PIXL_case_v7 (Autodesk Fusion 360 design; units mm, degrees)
part number: 0.96Oled_W_4_Buttons
base_feature "Base Feature"
work_plane "WorkPlane1" AlongDistance -6.5 ExtraOffset 0
sketch "Sketch1" plane through (0, 0, -6.5) normal (0, 0, 1) x axis (1, 0, 0)
  line L1 (24.2, -27.5) -> (-24.2, -27.5)
  line L2 (24.2, 15.7) -> (24.2, -27.5)
  line L3 (-24.2, 15.7) -> (24.2, 15.7)
  line L4 (-24.2, -27.5) -> (-24.2, 15.7)
extrude "Extrude1" new body sketch "Sketch1" along normal blind 11.8
fillet "Fillet1" radius 5
fillet "Fillet2" radius 1.4
work_plane "WorkPlane2" AlongDistance -6.5 ExtraOffset 0
sketch "Sketch2" plane through (0, 0, -6.5) normal (0, 0, 1) x axis (1, 0, 0)
  line L1 (22.2, -25.5) -> (-22.2, -25.5)
  line L2 (22.2, 13.7) -> (22.2, -25.5)
  line L3 (-22.2, 13.7) -> (22.2, 13.7)
  line L4 (-22.2, -25.5) -> (-22.2, 13.7)
extrude "Extrude2" cut sketch "Sketch2" along normal blind 9.3
fillet "Fillet3" radius 1.7
work_plane "WorkPlane3" AlongDistance 2.79 ExtraOffset 0
sketch "Sketch3" plane through (0, 0, 2.79) normal (0, 0, 1) x axis (1, 0, 0)
  line L1 (20.7, -11.3) -> (11, -11.3)
  line L2 (20.7, 11.7) -> (20.7, -11.3)
  line L3 (11, 11.7) -> (20.7, 11.7)
  line L4 (11, -11.3) -> (11, 11.7)
extrude "Extrude3" cut sketch "Sketch3" along normal blind 1.56
work_plane "WorkPlane4" AlongDistance 2.79 ExtraOffset 0
sketch "Sketch4" plane through (0, 0, 2.79) normal (0, 0, 1) x axis (1, 0, 0)
  line L1 (10, 9.6) -> (-10.8, 9.6)
  line L2 (10, 12.2) -> (10, 9.6)
  line L3 (-10.8, 12.2) -> (10, 12.2)
  line L4 (-10.8, 9.6) -> (-10.8, 12.2)
extrude "Extrude4" cut sketch "Sketch4" along normal blind 0.91
work_plane "WorkPlane5" AlongDistance 4.34 ExtraOffset 0
sketch "Sketch5" plane through (0, 0, 4.34) normal (0, 0, 1) x axis (1, 0, 0)
  line L1 (12.1, 5.6) -> (11.5, 5.6)
  line L2 (12.1, 11.8) -> (12.1, 5.6)
  line L3 (11.5, 11.8) -> (12.1, 11.8)
  line L4 (11.5, 5.6) -> (11.5, 11.8)
extrude "Extrude5" cut sketch "Sketch5" along normal blind 1.06
work_plane "WorkPlane6" AlongDistance 4.34 ExtraOffset 0
sketch "Sketch6" plane through (0, 0, 4.34) normal (0, 0, 1) x axis (1, 0, 0)
  line L1 (19.6, 11.2) -> (11.5, 11.2)
  line L2 (19.6, 11.8) -> (19.6, 11.2)
  line L3 (11.5, 11.8) -> (19.6, 11.8)
  line L4 (11.5, 11.2) -> (11.5, 11.8)
extrude "Extrude6" cut sketch "Sketch6" along normal blind 1.06
work_plane "WorkPlane7" AlongDistance 4.34 ExtraOffset 0
sketch "Sketch7" plane through (0, 0, 4.34) normal (0, 0, 1) x axis (1, 0, 0)
  line L1 (19.6, 5.6) -> (11.5, 5.6)
  line L2 (19.6, 6.2) -> (19.6, 5.6)
  line L3 (11.5, 6.2) -> (19.6, 6.2)
  line L4 (11.5, 5.6) -> (11.5, 6.2)
extrude "Extrude7" cut sketch "Sketch7" along normal blind 1.06
work_plane "WorkPlane8" AlongDistance 4.34 ExtraOffset 0
sketch "Sketch8" plane through (0, 0, 4.34) normal (0, 0, 1) x axis (1, 0, 0)
  line L1 (12.1, -0.07) -> (11.5, -0.07)
  line L2 (12.1, 6.13) -> (12.1, -0.07)
  line L3 (11.5, 6.13) -> (12.1, 6.13)
  line L4 (11.5, -0.07) -> (11.5, 6.13)
extrude "Extrude8" cut sketch "Sketch8" along normal blind 1.06
work_plane "WorkPlane9" AlongDistance 4.34 ExtraOffset 0
sketch "Sketch9" plane through (0, 0, 4.34) normal (0, 0, 1) x axis (1, 0, 0)
  line L1 (19.6, 5.53) -> (11.5, 5.53)
  line L2 (19.6, 6.13) -> (19.6, 5.53)
  line L3 (11.5, 6.13) -> (19.6, 6.13)
  line L4 (11.5, 5.53) -> (11.5, 6.13)
extrude "Extrude9" cut sketch "Sketch9" along normal blind 1.06
work_plane "WorkPlane10" AlongDistance 4.34 ExtraOffset 0
sketch "Sketch10" plane through (0, 0, 4.34) normal (0, 0, 1) x axis (1, 0, 0)
  line L1 (19.6, -0.07) -> (11.5, -0.07)
  line L2 (19.6, 0.53) -> (19.6, -0.07)
  line L3 (11.5, 0.53) -> (19.6, 0.53)
  line L4 (11.5, -0.07) -> (11.5, 0.53)
extrude "Extrude10" cut sketch "Sketch10" along normal blind 1.06
work_plane "WorkPlane11" AlongDistance 4.34 ExtraOffset 0
sketch "Sketch11" plane through (0, 0, 4.34) normal (0, 0, 1) x axis (1, 0, 0)
  line L1 (12.1, -5.73) -> (11.5, -5.73)
  line L2 (12.1, 0.47) -> (12.1, -5.73)
  line L3 (11.5, 0.47) -> (12.1, 0.47)
  line L4 (11.5, -5.73) -> (11.5, 0.47)
extrude "Extrude11" cut sketch "Sketch11" along normal blind 1.06
work_plane "WorkPlane12" AlongDistance 4.34 ExtraOffset 0
sketch "Sketch12" plane through (0, 0, 4.34) normal (0, 0, 1) x axis (1, 0, 0)
  line L1 (19.6, -0.13) -> (11.5, -0.13)
  line L2 (19.6, 0.47) -> (19.6, -0.13)
  line L3 (11.5, 0.47) -> (19.6, 0.47)
  line L4 (11.5, -0.13) -> (11.5, 0.47)
extrude "Extrude12" cut sketch "Sketch12" along normal blind 1.06
work_plane "WorkPlane13" AlongDistance 4.34 ExtraOffset 0
sketch "Sketch13" plane through (0, 0, 4.34) normal (0, 0, 1) x axis (1, 0, 0)
  line L1 (19.6, -5.73) -> (11.5, -5.73)
  line L2 (19.6, -5.13) -> (19.6, -5.73)
  line L3 (11.5, -5.13) -> (19.6, -5.13)
  line L4 (11.5, -5.73) -> (11.5, -5.13)
extrude "Extrude13" cut sketch "Sketch13" along normal blind 1.06
work_plane "WorkPlane14" AlongDistance 4.34 ExtraOffset 0
sketch "Sketch14" plane through (0, 0, 4.34) normal (0, 0, 1) x axis (1, 0, 0)
  line L1 (12.1, -11.4) -> (11.5, -11.4)
  line L2 (12.1, -5.2) -> (12.1, -11.4)
  line L3 (11.5, -5.2) -> (12.1, -5.2)
  line L4 (11.5, -11.4) -> (11.5, -5.2)
extrude "Extrude14" cut sketch "Sketch14" along normal blind 1.06
work_plane "WorkPlane15" AlongDistance 4.34 ExtraOffset 0
sketch "Sketch15" plane through (0, 0, 4.34) normal (0, 0, 1) x axis (1, 0, 0)
  line L1 (19.6, -5.8) -> (11.5, -5.8)
  line L2 (19.6, -5.2) -> (19.6, -5.8)
  line L3 (11.5, -5.2) -> (19.6, -5.2)
  line L4 (11.5, -5.8) -> (11.5, -5.2)
extrude "Extrude15" cut sketch "Sketch15" along normal blind 1.06
work_plane "WorkPlane16" AlongDistance 4.34 ExtraOffset 0
sketch "Sketch16" plane through (0, 0, 4.34) normal (0, 0, 1) x axis (1, 0, 0)
  line L1 (19.6, -11.4) -> (11.5, -11.4)
  line L2 (19.6, -10.8) -> (19.6, -11.4)
  line L3 (11.5, -10.8) -> (19.6, -10.8)
  line L4 (11.5, -11.4) -> (11.5, -10.8)
extrude "Extrude16" cut sketch "Sketch16" along normal blind 1.06
work_plane "WorkPlane17" AlongDistance 4.34 ExtraOffset 0
sketch "Sketch17" plane through (0, 0, 4.34) normal (0, 0, 1) x axis (1, 0, 0)
  line L1 (20.7, 6.2) -> (18.4, 6.2)
  line L2 (20.7, 11.2) -> (20.7, 6.2)
  line L3 (18.4, 11.2) -> (20.7, 11.2)
  line L4 (18.4, 6.2) -> (18.4, 11.2)
extrude "Extrude17" cut sketch "Sketch17" along normal blind 0.46
work_plane "WorkPlane18" AlongDistance 4.34 ExtraOffset 0
sketch "Sketch18" plane through (0, 0, 4.34) normal (0, 0, 1) x axis (1, 0, 0)
  line L1 (20.7, 0.53) -> (18.4, 0.53)
  line L2 (20.7, 5.53) -> (20.7, 0.53)
  line L3 (18.4, 5.53) -> (20.7, 5.53)
  line L4 (18.4, 0.53) -> (18.4, 5.53)
extrude "Extrude18" cut sketch "Sketch18" along normal blind 0.46
work_plane "WorkPlane19" AlongDistance 4.34 ExtraOffset 0
sketch "Sketch19" plane through (0, 0, 4.34) normal (0, 0, 1) x axis (1, 0, 0)
  line L1 (20.7, -5.13) -> (18.4, -5.13)
  line L2 (20.7, -0.13) -> (20.7, -5.13)
  line L3 (18.4, -0.13) -> (20.7, -0.13)
  line L4 (18.4, -5.13) -> (18.4, -0.13)
extrude "Extrude19" cut sketch "Sketch19" along normal blind 0.46
work_plane "WorkPlane20" AlongDistance 4.34 ExtraOffset 0
sketch "Sketch20" plane through (0, 0, 4.34) normal (0, 0, 1) x axis (1, 0, 0)
  line L1 (20.7, -10.8) -> (18.4, -10.8)
  line L2 (20.7, -5.8) -> (20.7, -10.8)
  line L3 (18.4, -5.8) -> (20.7, -5.8)
  line L4 (18.4, -10.8) -> (18.4, -5.8)
extrude "Extrude20" cut sketch "Sketch20" along normal blind 0.46
work_plane "WorkPlane21" AlongDistance 2.79 ExtraOffset 0
sketch "Sketch21" plane through (0, 0, 2.79) normal (0, 0, 1) x axis (1, 0, 0)
  line L1 (7, -6.6) -> (-16.3, -6.6)
  line L2 (7, 6.4) -> (7, -6.6)
  line L3 (-16.3, 6.4) -> (7, 6.4)
  line L4 (-16.3, -6.6) -> (-16.3, 6.4)
extrude "Extrude21" cut sketch "Sketch21" along normal blind 2.61
chamfer "Chamfer1" distance 1.2
work_plane "WorkPlane22" AlongDistance 1.6 ExtraOffset 0
sketch "Sketch22" plane through (0, 0, 1.6) normal (0, 0, 1) x axis (1, 0, 0)
  circle C1 centre (-20.5, -12) radius 1.5
extrude "Extrude22" add sketch "Sketch22" along normal blind 1.21
work_plane "WorkPlane23" AlongDistance 0.3 ExtraOffset 0
sketch "Sketch23" plane through (0, 0, 0.3) normal (0, 0, 1) x axis (1, 0, 0)
  circle C1 centre (-20.5, -12) radius 0.88
extrude "Extrude23" add sketch "Sketch23" along normal blind 1.31
work_plane "WorkPlane24" AlongDistance 1.6 ExtraOffset 0
sketch "Sketch24" plane through (0, 0, 1.6) normal (0, 0, 1) x axis (1, 0, 0)
  circle C1 centre (-20.5, 12) radius 1.5
extrude "Extrude24" add sketch "Sketch24" along normal blind 1.21
work_plane "WorkPlane25" AlongDistance 0.3 ExtraOffset 0
sketch "Sketch25" plane through (0, 0, 0.3) normal (0, 0, 1) x axis (1, 0, 0)
  circle C1 centre (-20.5, 12) radius 0.88
extrude "Extrude25" add sketch "Sketch25" along normal blind 1.31
work_plane "WorkPlane26" AlongDistance 1.6 ExtraOffset 0
sketch "Sketch26" plane through (0, 0, 1.6) normal (0, 0, 1) x axis (1, 0, 0)
  circle C1 centre (20.5, -12) radius 1.5
extrude "Extrude26" add sketch "Sketch26" along normal blind 1.21
work_plane "WorkPlane27" AlongDistance 0.3 ExtraOffset 0
sketch "Sketch27" plane through (0, 0, 0.3) normal (0, 0, 1) x axis (1, 0, 0)
  circle C1 centre (20.5, -12) radius 0.88
extrude "Extrude27" add sketch "Sketch27" along normal blind 1.31
work_plane "WorkPlane28" AlongDistance 1.6 ExtraOffset 0
sketch "Sketch28" plane through (0, 0, 1.6) normal (0, 0, 1) x axis (1, 0, 0)
  circle C1 centre (20.5, 12) radius 1.5
extrude "Extrude28" add sketch "Sketch28" along normal blind 1.21
work_plane "WorkPlane29" AlongDistance 0.3 ExtraOffset 0
sketch "Sketch29" plane through (0, 0, 0.3) normal (0, 0, 1) x axis (1, 0, 0)
  circle C1 centre (20.5, 12) radius 0.88
extrude "Extrude29" add sketch "Sketch29" along normal blind 1.31
work_plane "WorkPlane30" AlongDistance 5.3 ExtraOffset 0
sketch "Sketch30" plane through (0, 0, 5.3) normal (0, 0, 1) x axis (1, 0, 0)
  line L1 (-16.5, -17.8) -> (-19.8, -17.8)
  line L2 (-16.5, -16.7) -> (-16.5, -17.8)
  line L3 (-19.8, -16.7) -> (-16.5, -16.7)
  line L4 (-19.8, -17.8) -> (-19.8, -16.7)
  line L5 (-18.7, -18.9) -> (-19.8, -18.9)
  line L6 (-18.7, -17.8) -> (-18.7, -18.9)
  line L7 (-19.8, -17.8) -> (-18.7, -17.8)
  line L8 (-19.8, -18.9) -> (-19.8, -17.8)
  line L9 (-15.4, -18.9) -> (-16.5, -18.9)
  line L10 (-15.4, -17.8) -> (-15.4, -18.9)
  line L11 (-16.5, -17.8) -> (-15.4, -17.8)
  line L12 (-16.5, -18.9) -> (-16.5, -17.8)
  line L13 (-18.7, -20) -> (-19.8, -20)
  line L14 (-18.7, -18.9) -> (-18.7, -20)
  line L15 (-19.8, -18.9) -> (-18.7, -18.9)
  line L16 (-19.8, -20) -> (-19.8, -18.9)
  line L17 (-15.4, -20) -> (-16.5, -20)
  line L18 (-15.4, -18.9) -> (-15.4, -20)
  line L19 (-16.5, -18.9) -> (-15.4, -18.9)
  line L20 (-16.5, -20) -> (-16.5, -18.9)
  line L21 (-16.5, -21.1) -> (-19.8, -21.1)
  line L22 (-16.5, -20) -> (-16.5, -21.1)
  line L23 (-19.8, -20) -> (-16.5, -20)
  line L24 (-19.8, -21.1) -> (-19.8, -20)
  line L25 (-18.7, -22.2) -> (-19.8, -22.2)
  line L26 (-18.7, -21.1) -> (-18.7, -22.2)
  line L27 (-19.8, -21.1) -> (-18.7, -21.1)
  line L28 (-19.8, -22.2) -> (-19.8, -21.1)
  line L29 (-18.7, -23.3) -> (-19.8, -23.3)
  line L30 (-18.7, -22.2) -> (-18.7, -23.3)
  line L31 (-19.8, -22.2) -> (-18.7, -22.2)
  line L32 (-19.8, -23.3) -> (-19.8, -22.2)
  line L33 (-13.2, -17.8) -> (-14.3, -17.8)
  line L34 (-13.2, -16.7) -> (-13.2, -17.8)
  line L35 (-14.3, -16.7) -> (-13.2, -16.7)
  line L36 (-14.3, -17.8) -> (-14.3, -16.7)
  line L37 (-13.2, -20) -> (-14.3, -20)
  line L38 (-13.2, -18.9) -> (-13.2, -20)
  line L39 (-14.3, -18.9) -> (-13.2, -18.9)
  line L40 (-14.3, -20) -> (-14.3, -18.9)
  line L41 (-13.2, -21.1) -> (-14.3, -21.1)
  line L42 (-13.2, -20) -> (-13.2, -21.1)
  line L43 (-14.3, -20) -> (-13.2, -20)
  line L44 (-14.3, -21.1) -> (-14.3, -20)
  line L45 (-13.2, -22.2) -> (-14.3, -22.2)
  line L46 (-13.2, -21.1) -> (-13.2, -22.2)
  line L47 (-14.3, -21.1) -> (-13.2, -21.1)
  line L48 (-14.3, -22.2) -> (-14.3, -21.1)
  line L49 (-13.2, -23.3) -> (-14.3, -23.3)
  line L50 (-13.2, -22.2) -> (-13.2, -23.3)
  line L51 (-14.3, -22.2) -> (-13.2, -22.2)
  line L52 (-14.3, -23.3) -> (-14.3, -22.2)
  line L53 (-11, -17.8) -> (-12.1, -17.8)
  line L54 (-11, -16.7) -> (-11, -17.8)
  line L55 (-12.1, -16.7) -> (-11, -16.7)
  line L56 (-12.1, -17.8) -> (-12.1, -16.7)
  line L57 (-7.7, -17.8) -> (-8.8, -17.8)
  line L58 (-7.7, -16.7) -> (-7.7, -17.8)
  line L59 (-8.8, -16.7) -> (-7.7, -16.7)
  line L60 (-8.8, -17.8) -> (-8.8, -16.7)
  line L61 (-11, -18.9) -> (-12.1, -18.9)
  line L62 (-11, -17.8) -> (-11, -18.9)
  line L63 (-12.1, -17.8) -> (-11, -17.8)
  line L64 (-12.1, -18.9) -> (-12.1, -17.8)
  line L65 (-7.7, -18.9) -> (-8.8, -18.9)
  line L66 (-7.7, -17.8) -> (-7.7, -18.9)
  line L67 (-8.8, -17.8) -> (-7.7, -17.8)
  line L68 (-8.8, -18.9) -> (-8.8, -17.8)
  line L69 (-8.8, -20) -> (-11, -20)
  line L70 (-8.8, -18.9) -> (-8.8, -20)
  line L71 (-11, -18.9) -> (-8.8, -18.9)
  line L72 (-11, -20) -> (-11, -18.9)
  line L73 (-8.8, -21.1) -> (-11, -21.1)
  line L74 (-8.8, -20) -> (-8.8, -21.1)
  line L75 (-11, -20) -> (-8.8, -20)
  line L76 (-11, -21.1) -> (-11, -20)
  line L77 (-11, -22.2) -> (-12.1, -22.2)
  line L78 (-11, -21.1) -> (-11, -22.2)
  line L79 (-12.1, -21.1) -> (-11, -21.1)
  line L80 (-12.1, -22.2) -> (-12.1, -21.1)
  line L81 (-7.7, -22.2) -> (-8.8, -22.2)
  line L82 (-7.7, -21.1) -> (-7.7, -22.2)
  line L83 (-8.8, -21.1) -> (-7.7, -21.1)
  line L84 (-8.8, -22.2) -> (-8.8, -21.1)
  line L85 (-11, -23.3) -> (-12.1, -23.3)
  line L86 (-11, -22.2) -> (-11, -23.3)
  line L87 (-12.1, -22.2) -> (-11, -22.2)
  line L88 (-12.1, -23.3) -> (-12.1, -22.2)
  line L89 (-7.7, -23.3) -> (-8.8, -23.3)
  line L90 (-7.7, -22.2) -> (-7.7, -23.3)
  line L91 (-8.8, -22.2) -> (-7.7, -22.2)
  line L92 (-8.8, -23.3) -> (-8.8, -22.2)
  line L93 (-5.5, -17.8) -> (-6.6, -17.8)
  line L94 (-5.5, -16.7) -> (-5.5, -17.8)
  line L95 (-6.6, -16.7) -> (-5.5, -16.7)
  line L96 (-6.6, -17.8) -> (-6.6, -16.7)
  line L97 (-5.5, -18.9) -> (-6.6, -18.9)
  line L98 (-5.5, -17.8) -> (-5.5, -18.9)
  line L99 (-6.6, -17.8) -> (-5.5, -17.8)
  line L100 (-6.6, -18.9) -> (-6.6, -17.8)
  line L101 (-5.5, -20) -> (-6.6, -20)
  line L102 (-5.5, -18.9) -> (-5.5, -20)
  line L103 (-6.6, -18.9) -> (-5.5, -18.9)
  line L104 (-6.6, -20) -> (-6.6, -18.9)
  line L105 (-5.5, -21.1) -> (-6.6, -21.1)
  line L106 (-5.5, -20) -> (-5.5, -21.1)
  line L107 (-6.6, -20) -> (-5.5, -20)
  line L108 (-6.6, -21.1) -> (-6.6, -20)
  line L109 (-5.5, -22.2) -> (-6.6, -22.2)
  line L110 (-5.5, -21.1) -> (-5.5, -22.2)
  line L111 (-6.6, -21.1) -> (-5.5, -21.1)
  line L112 (-6.6, -22.2) -> (-6.6, -21.1)
  line L113 (-2.2, -23.3) -> (-6.6, -23.3)
  line L114 (-2.2, -22.2) -> (-2.2, -23.3)
  line L115 (-6.6, -22.2) -> (-2.2, -22.2)
  line L116 (-6.6, -23.3) -> (-6.6, -22.2)
extrude "Extrude30" cut sketch "Sketch30" against normal blind 0.4
work_plane "WorkPlane31" AlongDistance 5.3 ExtraOffset 0
sketch "Sketch31" plane through (0, 0, 5.3) normal (0, 0, 1) x axis (1, 0, 0)
  line L1 (3.25, -22.25) -> (2.5, -22.25)
  line L2 (3.25, -21.5) -> (3.25, -22.25)
  line L3 (2.5, -21.5) -> (3.25, -21.5)
  line L4 (2.5, -22.25) -> (2.5, -21.5)
  line L5 (4.5, -22.25) -> (3.75, -22.25)
  line L6 (4.5, -21.5) -> (4.5, -22.25)
  line L7 (3.75, -21.5) -> (4.5, -21.5)
  line L8 (3.75, -22.25) -> (3.75, -21.5)
  line L9 (5.75, -22.25) -> (5, -22.25)
  line L10 (5.75, -21.5) -> (5.75, -22.25)
  line L11 (5, -21.5) -> (5.75, -21.5)
  line L12 (5, -22.25) -> (5, -21.5)
  line L13 (7, -22.25) -> (6.25, -22.25)
  line L14 (7, -21.5) -> (7, -22.25)
  line L15 (6.25, -21.5) -> (7, -21.5)
  line L16 (6.25, -22.25) -> (6.25, -21.5)
  line L17 (8.25, -22.25) -> (7.5, -22.25)
  line L18 (8.25, -21.5) -> (8.25, -22.25)
  line L19 (7.5, -21.5) -> (8.25, -21.5)
  line L20 (7.5, -22.25) -> (7.5, -21.5)
  line L21 (9.5, -22.25) -> (8.75, -22.25)
  line L22 (9.5, -21.5) -> (9.5, -22.25)
  line L23 (8.75, -21.5) -> (9.5, -21.5)
  line L24 (8.75, -22.25) -> (8.75, -21.5)
  line L25 (10.75, -22.25) -> (10, -22.25)
  line L26 (10.75, -21.5) -> (10.75, -22.25)
  line L27 (10, -21.5) -> (10.75, -21.5)
  line L28 (10, -22.25) -> (10, -21.5)
  line L29 (13.25, -22.25) -> (12.5, -22.25)
  line L30 (13.25, -21.5) -> (13.25, -22.25)
  line L31 (12.5, -21.5) -> (13.25, -21.5)
  line L32 (12.5, -22.25) -> (12.5, -21.5)
  line L33 (15.75, -22.25) -> (15, -22.25)
  line L34 (15.75, -21.5) -> (15.75, -22.25)
  line L35 (15, -21.5) -> (15.75, -21.5)
  line L36 (15, -22.25) -> (15, -21.5)
  line L37 (3.25, -21) -> (2.5, -21)
  line L38 (3.25, -20.25) -> (3.25, -21)
  line L39 (2.5, -20.25) -> (3.25, -20.25)
  line L40 (2.5, -21) -> (2.5, -20.25)
  line L41 (4.5, -21) -> (3.75, -21)
  line L42 (4.5, -20.25) -> (4.5, -21)
  line L43 (3.75, -20.25) -> (4.5, -20.25)
  line L44 (3.75, -21) -> (3.75, -20.25)
  line L45 (7, -21) -> (6.25, -21)
  line L46 (7, -20.25) -> (7, -21)
  line L47 (6.25, -20.25) -> (7, -20.25)
  line L48 (6.25, -21) -> (6.25, -20.25)
  line L49 (9.5, -21) -> (8.75, -21)
  line L50 (9.5, -20.25) -> (9.5, -21)
  line L51 (8.75, -20.25) -> (9.5, -20.25)
  line L52 (8.75, -21) -> (8.75, -20.25)
  line L53 (12, -21) -> (11.25, -21)
  line L54 (12, -20.25) -> (12, -21)
  line L55 (11.25, -20.25) -> (12, -20.25)
  line L56 (11.25, -21) -> (11.25, -20.25)
  line L57 (3.25, -19.75) -> (2.5, -19.75)
  line L58 (3.25, -19) -> (3.25, -19.75)
  line L59 (2.5, -19) -> (3.25, -19)
  line L60 (2.5, -19.75) -> (2.5, -19)
  line L61 (4.5, -19.75) -> (3.75, -19.75)
  line L62 (4.5, -19) -> (4.5, -19.75)
  line L63 (3.75, -19) -> (4.5, -19)
  line L64 (3.75, -19.75) -> (3.75, -19)
  line L65 (5.75, -19.75) -> (5, -19.75)
  line L66 (5.75, -19) -> (5.75, -19.75)
  line L67 (5, -19) -> (5.75, -19)
  line L68 (5, -19.75) -> (5, -19)
  line L69 (7, -19.75) -> (6.25, -19.75)
  line L70 (7, -19) -> (7, -19.75)
  line L71 (6.25, -19) -> (7, -19)
  line L72 (6.25, -19.75) -> (6.25, -19)
  line L73 (8.25, -19.75) -> (7.5, -19.75)
  line L74 (8.25, -19) -> (8.25, -19.75)
  line L75 (7.5, -19) -> (8.25, -19)
  line L76 (7.5, -19.75) -> (7.5, -19)
  line L77 (10.75, -19.75) -> (10, -19.75)
  line L78 (10.75, -19) -> (10.75, -19.75)
  line L79 (10, -19) -> (10.75, -19)
  line L80 (10, -19.75) -> (10, -19)
  line L81 (13.25, -19.75) -> (12.5, -19.75)
  line L82 (13.25, -19) -> (13.25, -19.75)
  line L83 (12.5, -19) -> (13.25, -19)
  line L84 (12.5, -19.75) -> (12.5, -19)
  line L85 (15.75, -19.75) -> (15, -19.75)
  line L86 (15.75, -19) -> (15.75, -19.75)
  line L87 (15, -19) -> (15.75, -19)
  line L88 (15, -19.75) -> (15, -19)
  line L89 (3.25, -18.5) -> (2.5, -18.5)
  line L90 (3.25, -17.75) -> (3.25, -18.5)
  line L91 (2.5, -17.75) -> (3.25, -17.75)
  line L92 (2.5, -18.5) -> (2.5, -17.75)
  line L93 (4.5, -18.5) -> (3.75, -18.5)
  line L94 (4.5, -17.75) -> (4.5, -18.5)
  line L95 (3.75, -17.75) -> (4.5, -17.75)
  line L96 (3.75, -18.5) -> (3.75, -17.75)
  line L97 (7, -18.5) -> (6.25, -18.5)
  line L98 (7, -17.75) -> (7, -18.5)
  line L99 (6.25, -17.75) -> (7, -17.75)
  line L100 (6.25, -18.5) -> (6.25, -17.75)
  line L101 (9.5, -18.5) -> (8.75, -18.5)
  line L102 (9.5, -17.75) -> (9.5, -18.5)
  line L103 (8.75, -17.75) -> (9.5, -17.75)
  line L104 (8.75, -18.5) -> (8.75, -17.75)
  line L105 (12, -18.5) -> (11.25, -18.5)
  line L106 (12, -17.75) -> (12, -18.5)
  line L107 (11.25, -17.75) -> (12, -17.75)
  line L108 (11.25, -18.5) -> (11.25, -17.75)
extrude "Extrude31" cut sketch "Sketch31" against normal blind 0.35
work_plane "WorkPlane32" AlongDistance 5.3 ExtraOffset 0
sketch "Sketch32" plane through (0, 0, 5.3) normal (0, 0, 1) x axis (1, 0, 0)
  line L1 (17.125, 9.375) -> (16.675, 9.375)
  line L2 (17.125, 9.825) -> (17.125, 9.375)
  line L3 (16.675, 9.825) -> (17.125, 9.825)
  line L4 (16.675, 9.375) -> (16.675, 9.825)
  line L5 (17.575, 8.925) -> (16.225, 8.925)
  line L6 (17.575, 9.375) -> (17.575, 8.925)
  line L7 (16.225, 9.375) -> (17.575, 9.375)
  line L8 (16.225, 8.925) -> (16.225, 9.375)
  line L9 (16.675, 8.475) -> (15.775, 8.475)
  line L10 (16.675, 8.925) -> (16.675, 8.475)
  line L11 (15.775, 8.925) -> (16.675, 8.925)
  line L12 (15.775, 8.475) -> (15.775, 8.925)
  line L13 (18.025, 8.475) -> (17.125, 8.475)
  line L14 (18.025, 8.925) -> (18.025, 8.475)
  line L15 (17.125, 8.925) -> (18.025, 8.925)
  line L16 (17.125, 8.475) -> (17.125, 8.925)
  line L17 (16.225, 8.025) -> (15.325, 8.025)
  line L18 (16.225, 8.475) -> (16.225, 8.025)
  line L19 (15.325, 8.475) -> (16.225, 8.475)
  line L20 (15.325, 8.025) -> (15.325, 8.475)
  line L21 (18.475, 8.025) -> (17.575, 8.025)
  line L22 (18.475, 8.475) -> (18.475, 8.025)
  line L23 (17.575, 8.475) -> (18.475, 8.475)
  line L24 (17.575, 8.025) -> (17.575, 8.475)
  line L25 (15.775, 7.575) -> (15.325, 7.575)
  line L26 (15.775, 8.025) -> (15.775, 7.575)
  line L27 (15.325, 8.025) -> (15.775, 8.025)
  line L28 (15.325, 7.575) -> (15.325, 8.025)
  line L29 (18.475, 7.575) -> (18.025, 7.575)
  line L30 (18.475, 8.025) -> (18.475, 7.575)
  line L31 (18.025, 8.025) -> (18.475, 8.025)
  line L32 (18.025, 7.575) -> (18.025, 8.025)
  line L33 (15.775, 3.705) -> (15.325, 3.705)
  line L34 (15.775, 4.155) -> (15.775, 3.705)
  line L35 (15.325, 4.155) -> (15.775, 4.155)
  line L36 (15.325, 3.705) -> (15.325, 4.155)
  line L37 (18.475, 3.705) -> (18.025, 3.705)
  line L38 (18.475, 4.155) -> (18.475, 3.705)
  line L39 (18.025, 4.155) -> (18.475, 4.155)
  line L40 (18.025, 3.705) -> (18.025, 4.155)
  line L41 (16.225, 3.255) -> (15.325, 3.255)
  line L42 (16.225, 3.705) -> (16.225, 3.255)
  line L43 (15.325, 3.705) -> (16.225, 3.705)
  line L44 (15.325, 3.255) -> (15.325, 3.705)
  line L45 (18.475, 3.255) -> (17.575, 3.255)
  line L46 (18.475, 3.705) -> (18.475, 3.255)
  line L47 (17.575, 3.705) -> (18.475, 3.705)
  line L48 (17.575, 3.255) -> (17.575, 3.705)
  line L49 (16.675, 2.805) -> (15.775, 2.805)
  line L50 (16.675, 3.255) -> (16.675, 2.805)
  line L51 (15.775, 3.255) -> (16.675, 3.255)
  line L52 (15.775, 2.805) -> (15.775, 3.255)
  line L53 (18.025, 2.805) -> (17.125, 2.805)
  line L54 (18.025, 3.255) -> (18.025, 2.805)
  line L55 (17.125, 3.255) -> (18.025, 3.255)
  line L56 (17.125, 2.805) -> (17.125, 3.255)
  line L57 (17.575, 2.355) -> (16.225, 2.355)
  line L58 (17.575, 2.805) -> (17.575, 2.355)
  line L59 (16.225, 2.805) -> (17.575, 2.805)
  line L60 (16.225, 2.355) -> (16.225, 2.805)
  line L61 (17.125, 1.905) -> (16.675, 1.905)
  line L62 (17.125, 2.355) -> (17.125, 1.905)
  line L63 (16.675, 2.355) -> (17.125, 2.355)
  line L64 (16.675, 1.905) -> (16.675, 2.355)
  line L65 (18.475, -1.955) -> (15.325, -1.955)
  line L66 (18.475, -1.505) -> (18.475, -1.955)
  line L67 (15.325, -1.505) -> (18.475, -1.505)
  line L68 (15.325, -1.955) -> (15.325, -1.505)
  line L69 (18.475, -2.855) -> (15.325, -2.855)
  line L70 (18.475, -2.405) -> (18.475, -2.855)
  line L71 (15.325, -2.405) -> (18.475, -2.405)
  line L72 (15.325, -2.855) -> (15.325, -2.405)
  line L73 (18.475, -3.755) -> (15.325, -3.755)
  line L74 (18.475, -3.305) -> (18.475, -3.755)
  line L75 (15.325, -3.305) -> (18.475, -3.305)
  line L76 (15.325, -3.755) -> (15.325, -3.305)
  line L77 (16.675, -7.175) -> (16.225, -7.175)
  line L78 (16.675, -6.725) -> (16.675, -7.175)
  line L79 (16.225, -6.725) -> (16.675, -6.725)
  line L80 (16.225, -7.175) -> (16.225, -6.725)
  line L81 (16.675, -7.625) -> (15.775, -7.625)
  line L82 (16.675, -7.175) -> (16.675, -7.625)
  line L83 (15.775, -7.175) -> (16.675, -7.175)
  line L84 (15.775, -7.625) -> (15.775, -7.175)
  line L85 (18.025, -8.075) -> (15.325, -8.075)
  line L86 (18.025, -7.625) -> (18.025, -8.075)
  line L87 (15.325, -7.625) -> (18.025, -7.625)
  line L88 (15.325, -8.075) -> (15.325, -7.625)
  line L89 (16.675, -8.525) -> (15.775, -8.525)
  line L90 (16.675, -8.075) -> (16.675, -8.525)
  line L91 (15.775, -8.075) -> (16.675, -8.075)
  line L92 (15.775, -8.525) -> (15.775, -8.075)
  line L93 (18.475, -8.525) -> (18.025, -8.525)
  line L94 (18.475, -8.075) -> (18.475, -8.525)
  line L95 (18.025, -8.075) -> (18.475, -8.075)
  line L96 (18.025, -8.525) -> (18.025, -8.075)
  line L97 (16.675, -8.975) -> (16.225, -8.975)
  line L98 (16.675, -8.525) -> (16.675, -8.975)
  line L99 (16.225, -8.525) -> (16.675, -8.525)
  line L100 (16.225, -8.975) -> (16.225, -8.525)
  line L101 (18.475, -8.975) -> (18.025, -8.975)
  line L102 (18.475, -8.525) -> (18.475, -8.975)
  line L103 (18.025, -8.525) -> (18.475, -8.525)
  line L104 (18.025, -8.975) -> (18.025, -8.525)
  line L105 (18.475, -9.425) -> (18.025, -9.425)
  line L106 (18.475, -8.975) -> (18.475, -9.425)
  line L107 (18.025, -8.975) -> (18.475, -8.975)
  line L108 (18.025, -9.425) -> (18.025, -8.975)
  line L109 (18.025, -9.875) -> (15.775, -9.875)
  line L110 (18.025, -9.425) -> (18.025, -9.875)
  line L111 (15.775, -9.425) -> (18.025, -9.425)
  line L112 (15.775, -9.875) -> (15.775, -9.425)
extrude "Extrude32" cut sketch "Sketch32" against normal blind 0.3
work_plane "WorkPlane33" AlongDistance -4.9 ExtraOffset 0
sketch "Sketch33" plane through (0, 0, -4.9) normal (0, 0, 1) x axis (1, 0, 0)
  line L1 (24.7, -21) -> (21.7, -21)
  line L2 (24.7, -11) -> (24.7, -21)
  line L3 (21.7, -11) -> (24.7, -11)
  line L4 (21.7, -21) -> (21.7, -11)
extrude "Extrude33" cut sketch "Sketch33" along normal blind 4
work_plane "WorkPlane34" AlongDistance -5.9 ExtraOffset 0
sketch "Sketch34" plane through (0, 0, -5.9) normal (0, 0, 1) x axis (1, 0, 0)
  line L1 (24.7, -22.5) -> (23.2, -22.5)
  line L2 (24.7, -9.5) -> (24.7, -22.5)
  line L3 (23.2, -9.5) -> (24.7, -9.5)
  line L4 (23.2, -22.5) -> (23.2, -9.5)
extrude "Extrude34" cut sketch "Sketch34" along normal blind 6
work_plane "WorkPlane35" AlongDistance -6.5 ExtraOffset 0
sketch "Sketch35" plane through (0, 0, -6.5) normal (0, 0, 1) x axis (1, 0, 0)
  circle C1 centre (20, 11.6) radius 2.2
extrude "Extrude35" add sketch "Sketch35" along normal blind 6.35
work_plane "WorkPlane36" AlongDistance -6.5 ExtraOffset 0
sketch "Sketch36" plane through (0, 0, -6.5) normal (0, 0, 1) x axis (1, 0, 0)
  line L1 (22.5, 9.4) -> (20, 9.4)
  line L2 (22.5, 13.8) -> (22.5, 9.4)
  line L3 (20, 13.8) -> (22.5, 13.8)
  line L4 (20, 9.4) -> (20, 13.8)
extrude "Extrude36" add sketch "Sketch36" along normal blind 6.35
work_plane "WorkPlane37" AlongDistance -6.5 ExtraOffset 0
sketch "Sketch37" plane through (0, 0, -6.5) normal (0, 0, 1) x axis (1, 0, 0)
  line L1 (22.2, 11.6) -> (17.8, 11.6)
  line L2 (22.2, 14) -> (22.2, 11.6)
  line L3 (17.8, 14) -> (22.2, 14)
  line L4 (17.8, 11.6) -> (17.8, 14)
extrude "Extrude37" add sketch "Sketch37" along normal blind 6.35
work_plane "WorkPlane38" AlongDistance -6.51 ExtraOffset 0
sketch "Sketch38" plane through (0, 0, -6.51) normal (0, 0, 1) x axis (1, 0, 0)
  circle C1 centre (20, 11.6) radius 0.85
extrude "Extrude38" cut sketch "Sketch38" along normal blind 5.51
work_plane "WorkPlane39" AlongDistance -6.5 ExtraOffset 0
sketch "Sketch39" plane through (0, 0, -6.5) normal (0, 0, 1) x axis (1, 0, 0)
  circle C1 centre (-20, -23.4) radius 2.2
extrude "Extrude39" add sketch "Sketch39" along normal blind 6.35
work_plane "WorkPlane40" AlongDistance -6.5 ExtraOffset 0
sketch "Sketch40" plane through (0, 0, -6.5) normal (0, 0, 1) x axis (1, 0, 0)
  line L1 (-20, -25.6) -> (-22.5, -25.6)
  line L2 (-20, -21.2) -> (-20, -25.6)
  line L3 (-22.5, -21.2) -> (-20, -21.2)
  line L4 (-22.5, -25.6) -> (-22.5, -21.2)
extrude "Extrude40" add sketch "Sketch40" along normal blind 6.35
work_plane "WorkPlane41" AlongDistance -6.5 ExtraOffset 0
sketch "Sketch41" plane through (0, 0, -6.5) normal (0, 0, 1) x axis (1, 0, 0)
  line L1 (-17.8, -25.8) -> (-22.2, -25.8)
  line L2 (-17.8, -23.4) -> (-17.8, -25.8)
  line L3 (-22.2, -23.4) -> (-17.8, -23.4)
  line L4 (-22.2, -25.8) -> (-22.2, -23.4)
extrude "Extrude41" add sketch "Sketch41" along normal blind 6.35
work_plane "WorkPlane42" AlongDistance -6.51 ExtraOffset 0
sketch "Sketch42" plane through (0, 0, -6.51) normal (0, 0, 1) x axis (1, 0, 0)
  circle C1 centre (-20, -23.4) radius 0.85
extrude "Extrude42" cut sketch "Sketch42" along normal blind 5.51
work_plane "WorkPlane43" AlongDistance -6.5 ExtraOffset 0
sketch "Sketch43" plane through (0, 0, -6.5) normal (0, 0, 1) x axis (1, 0, 0)
  circle C1 centre (-20.3, -8.9) radius 1.9
extrude "Extrude43" add sketch "Sketch43" along normal blind 6.35
work_plane "WorkPlane44" AlongDistance -6.5 ExtraOffset 0
sketch "Sketch44" plane through (0, 0, -6.5) normal (0, 0, 1) x axis (1, 0, 0)
  line L1 (-20.3, -10.8) -> (-22.5, -10.8)
  line L2 (-20.3, -7) -> (-20.3, -10.8)
  line L3 (-22.5, -7) -> (-20.3, -7)
  line L4 (-22.5, -10.8) -> (-22.5, -7)
extrude "Extrude44" add sketch "Sketch44" along normal blind 6.35
work_plane "WorkPlane45" AlongDistance -6.51 ExtraOffset 0
sketch "Sketch45" plane through (0, 0, -6.51) normal (0, 0, 1) x axis (1, 0, 0)
  circle C1 centre (-20.3, -8.9) radius 0.85
extrude "Extrude45" cut sketch "Sketch45" along normal blind 5.51
work_plane "WorkPlane46" AlongDistance -6.5 ExtraOffset 0
sketch "Sketch46" plane through (0, 0, -6.5) normal (0, 0, 1) x axis (1, 0, 0)
  circle C1 centre (20.3, -4) radius 1.9
extrude "Extrude46" add sketch "Sketch46" along normal blind 6.35
work_plane "WorkPlane47" AlongDistance -6.5 ExtraOffset 0
sketch "Sketch47" plane through (0, 0, -6.5) normal (0, 0, 1) x axis (1, 0, 0)
  line L1 (22.5, -5.9) -> (20.3, -5.9)
  line L2 (22.5, -2.1) -> (22.5, -5.9)
  line L3 (20.3, -2.1) -> (22.5, -2.1)
  line L4 (20.3, -5.9) -> (20.3, -2.1)
extrude "Extrude47" add sketch "Sketch47" along normal blind 6.35
work_plane "WorkPlane48" AlongDistance -6.51 ExtraOffset 0
sketch "Sketch48" plane through (0, 0, -6.51) normal (0, 0, 1) x axis (1, 0, 0)
  circle C1 centre (20.3, -4) radius 0.85
extrude "Extrude48" cut sketch "Sketch48" along normal blind 5.51
work_plane "WorkPlane49" AlongDistance -6.5 ExtraOffset 0
sketch "Sketch49" plane through (0, 0, -6.5) normal (0, 0, 1) x axis (1, 0, 0)
  line L1 (-10.2, -32.1) -> (-12.6, -32.1)
  line L2 (-10.2, -26.5) -> (-10.2, -32.1)
  line L3 (-12.6, -26.5) -> (-10.2, -26.5)
  line L4 (-12.6, -32.1) -> (-12.6, -26.5)
extrude "Extrude49" add sketch "Sketch49" along normal blind 3
work_plane "WorkPlane50" AlongDistance -7.7 ExtraOffset 0
sketch "Sketch50" plane through (0, 0, -7.7) normal (0, 0, 1) x axis (1, 0, 0)
  line L1 (-10.2, -32.1) -> (-12.6, -32.1)
  line L2 (-10.2, -27.7) -> (-10.2, -32.1)
  line L3 (-12.6, -27.7) -> (-10.2, -27.7)
  line L4 (-12.6, -32.1) -> (-12.6, -27.7)
extrude "Extrude50" add sketch "Sketch50" along normal blind 1.21
work_plane "WorkPlane51" AlongDistance -6.5 ExtraOffset 0
sketch "Sketch51" plane through (0, 0, -6.5) normal (0, 0, 1) x axis (1, 0, 0)
  line L1 (-10.2, 14.7) -> (-12.6, 14.7)
  line L2 (-10.2, 20.3) -> (-10.2, 14.7)
  line L3 (-12.6, 20.3) -> (-10.2, 20.3)
  line L4 (-12.6, 14.7) -> (-12.6, 20.3)
extrude "Extrude51" add sketch "Sketch51" along normal blind 3
work_plane "WorkPlane52" AlongDistance -7.7 ExtraOffset 0
sketch "Sketch52" plane through (0, 0, -7.7) normal (0, 0, 1) x axis (1, 0, 0)
  line L1 (-10.2, 15.9) -> (-12.6, 15.9)
  line L2 (-10.2, 20.3) -> (-10.2, 15.9)
  line L3 (-12.6, 20.3) -> (-10.2, 20.3)
  line L4 (-12.6, 15.9) -> (-12.6, 20.3)
extrude "Extrude52" add sketch "Sketch52" along normal blind 1.21
work_plane "WorkPlane53" AlongDistance -6.5 ExtraOffset 0
sketch "Sketch53" plane through (0, 0, -6.5) normal (0, 0, 1) x axis (1, 0, 0)
  line L1 (12.6, -32.1) -> (10.2, -32.1)
  line L2 (12.6, -26.5) -> (12.6, -32.1)
  line L3 (10.2, -26.5) -> (12.6, -26.5)
  line L4 (10.2, -32.1) -> (10.2, -26.5)
extrude "Extrude53" add sketch "Sketch53" along normal blind 3
work_plane "WorkPlane54" AlongDistance -7.7 ExtraOffset 0
sketch "Sketch54" plane through (0, 0, -7.7) normal (0, 0, 1) x axis (1, 0, 0)
  line L1 (12.6, -32.1) -> (10.2, -32.1)
  line L2 (12.6, -27.7) -> (12.6, -32.1)
  line L3 (10.2, -27.7) -> (12.6, -27.7)
  line L4 (10.2, -32.1) -> (10.2, -27.7)
extrude "Extrude54" add sketch "Sketch54" along normal blind 1.21
work_plane "WorkPlane55" AlongDistance -6.5 ExtraOffset 0
sketch "Sketch55" plane through (0, 0, -6.5) normal (0, 0, 1) x axis (1, 0, 0)
  line L1 (12.6, 14.7) -> (10.2, 14.7)
  line L2 (12.6, 20.3) -> (12.6, 14.7)
  line L3 (10.2, 20.3) -> (12.6, 20.3)
  line L4 (10.2, 14.7) -> (10.2, 20.3)
extrude "Extrude55" add sketch "Sketch55" along normal blind 3
work_plane "WorkPlane56" AlongDistance -7.7 ExtraOffset 0
sketch "Sketch56" plane through (0, 0, -7.7) normal (0, 0, 1) x axis (1, 0, 0)
  line L1 (12.6, 15.9) -> (10.2, 15.9)
  line L2 (12.6, 20.3) -> (12.6, 15.9)
  line L3 (10.2, 20.3) -> (12.6, 20.3)
  line L4 (10.2, 15.9) -> (10.2, 20.3)
extrude "Extrude56" add sketch "Sketch56" along normal blind 1.21
fillet "Fillet4" radius 1.2
sketch "Sketch57" plane through (0, 0, 0) normal (1, 0, 0) x axis (0, 0, -1)
  circle C1 centre (6.2, -30.3) radius 0.55
extrude "Extrude57" cut sketch "Sketch57" distance 13.6
sketch "Sketch58" plane through (0, 0, 0) normal (1, 0, 0) x axis (0, 0, -1)
  circle C1 centre (6.2, 18.5) radius 0.55
extrude "Extrude58" cut sketch "Sketch58" distance 13.6
work_plane "WorkPlane1" AlongDistance -7.7 ExtraOffset 0
sketch "Sketch1" plane through (0, 0, -7.7) normal (0, 0, 1) x axis (1, 0, 0)
  line L1 (24.2, -27.5) -> (-24.2, -27.5)
  line L2 (24.2, 15.7) -> (24.2, -27.5)
  line L3 (-24.2, 15.7) -> (24.2, 15.7)
  line L4 (-24.2, -27.5) -> (-24.2, 15.7)
extrude "Extrude1" new body sketch "Sketch1" along normal blind 1.2
fillet "Fillet1" radius 5
fillet "Fillet2" radius 0.6
work_plane "WorkPlane2" AlongDistance -7.8 ExtraOffset 0
sketch "Sketch2" plane through (0, 0, -7.8) normal (0, 0, 1) x axis (1, 0, 0)
  circle C1 centre (20, 11.6) radius 1.1
extrude "Extrude2" cut sketch "Sketch2" along normal blind 1.4
work_plane "WorkPlane3" AlongDistance -7.8 ExtraOffset 0
sketch "Sketch3" plane through (0, 0, -7.8) normal (0, 0, 1) x axis (1, 0, 0)
  circle C1 centre (20, 11.6) radius 1.95
extrude "Extrude3" cut sketch "Sketch3" along normal blind 0.8
work_plane "WorkPlane4" AlongDistance -7.8 ExtraOffset 0
sketch "Sketch4" plane through (0, 0, -7.8) normal (0, 0, 1) x axis (1, 0, 0)
  circle C1 centre (-20, -23.4) radius 1.1
extrude "Extrude4" cut sketch "Sketch4" along normal blind 1.4
work_plane "WorkPlane5" AlongDistance -7.8 ExtraOffset 0
sketch "Sketch5" plane through (0, 0, -7.8) normal (0, 0, 1) x axis (1, 0, 0)
  circle C1 centre (-20, -23.4) radius 1.95
extrude "Extrude5" cut sketch "Sketch5" along normal blind 0.8
work_plane "WorkPlane6" AlongDistance -7.8 ExtraOffset 0
sketch "Sketch6" plane through (0, 0, -7.8) normal (0, 0, 1) x axis (1, 0, 0)
  circle C1 centre (-20.3, -8.9) radius 1.1
extrude "Extrude6" cut sketch "Sketch6" along normal blind 1.4
work_plane "WorkPlane7" AlongDistance -7.8 ExtraOffset 0
sketch "Sketch7" plane through (0, 0, -7.8) normal (0, 0, 1) x axis (1, 0, 0)
  circle C1 centre (-20.3, -8.9) radius 1.95
extrude "Extrude7" cut sketch "Sketch7" along normal blind 0.8
work_plane "WorkPlane8" AlongDistance -7.8 ExtraOffset 0
sketch "Sketch8" plane through (0, 0, -7.8) normal (0, 0, 1) x axis (1, 0, 0)
  circle C1 centre (20.3, -4) radius 1.1
extrude "Extrude8" cut sketch "Sketch8" along normal blind 1.4
work_plane "WorkPlane9" AlongDistance -7.8 ExtraOffset 0
sketch "Sketch9" plane through (0, 0, -7.8) normal (0, 0, 1) x axis (1, 0, 0)
  circle C1 centre (20.3, -4) radius 1.95
extrude "Extrude9" cut sketch "Sketch9" along normal blind 0.8
work_plane "WorkPlane10" AlongDistance -6.51 ExtraOffset 0
sketch "Sketch10" plane through (0, 0, -6.51) normal (0, 0, 1) x axis (1, 0, 0)
  line L1 (21.95, -0.5) -> (20.95, -0.5)
  line L2 (21.95, 4) -> (21.95, -0.5)
  line L3 (20.95, 4) -> (21.95, 4)
  line L4 (20.95, -0.5) -> (20.95, 4)
extrude "Extrude10" add sketch "Sketch10" along normal blind 1.01
work_plane "WorkPlane11" AlongDistance -6.51 ExtraOffset 0
sketch "Sketch11" plane through (0, 0, -6.51) normal (0, 0, 1) x axis (1, 0, 0)
  line L1 (0.2, -25.25) -> (-3.2, -25.25)
  line L2 (0.2, -24.25) -> (0.2, -25.25)
  line L3 (-3.2, -24.25) -> (0.2, -24.25)
  line L4 (-3.2, -25.25) -> (-3.2, -24.25)
extrude "Extrude11" add sketch "Sketch11" along normal blind 1.01
work_plane "WorkPlane12" AlongDistance -6.8 ExtraOffset 0
sketch "Sketch12" plane through (0, 0, -6.8) normal (0, 0, 1) x axis (1, 0, 0)
  circle C1 centre (11, -15.3) radius 10.3
extrude "Extrude12" cut sketch "Sketch12" along normal blind 0.31
work_plane "WorkPlane13" AlongDistance -7.7 ExtraOffset 0
sketch "Sketch13" plane through (0, 0, -7.7) normal (0, 0, 1) x axis (1, 0, 0)
  line L1 (-11.95, -9.65) -> (-15.05, -9.65)
  line L2 (-9.75, -4.35) -> (-9.75, -7.45)
  line L3 (-15.05, -2.15) -> (-11.95, -2.15)
  line L4 (-17.25, -7.45) -> (-17.25, -4.35)
  line L5 (-11.95, -9.05) -> (-15.05, -9.05)
  line L6 (-10.35, -4.35) -> (-10.35, -7.45)
  line L7 (-15.05, -2.75) -> (-11.95, -2.75)
  line L8 (-16.65, -7.45) -> (-16.65, -4.35)
  arc A1 centre (-11.95, -7.45) radius 2.2 clockwise from (-9.75, -7.45) to (-11.95, -9.65)
  arc A2 centre (-11.95, -4.35) radius 2.2 clockwise from (-11.95, -2.15) to (-9.75, -4.35)
  arc A3 centre (-15.05, -4.35) radius 2.2 clockwise from (-17.25, -4.35) to (-15.05, -2.15)
  arc A4 centre (-15.05, -7.45) radius 2.2 clockwise from (-15.05, -9.65) to (-17.25, -7.45)
  arc A5 centre (-11.95, -7.45) radius 1.6 clockwise from (-10.35, -7.45) to (-11.95, -9.05)
  arc A6 centre (-11.95, -4.35) radius 1.6 clockwise from (-11.95, -2.75) to (-10.35, -4.35)
  arc A7 centre (-15.05, -4.35) radius 1.6 clockwise from (-16.65, -4.35) to (-15.05, -2.75)
  arc A8 centre (-15.05, -7.45) radius 1.6 clockwise from (-15.05, -9.05) to (-16.65, -7.45)
extrude "Extrude13" cut sketch "Sketch13" along normal blind 0.3
work_plane "WorkPlane14" AlongDistance -7.7 ExtraOffset 0
sketch "Sketch14" plane through (0, 0, -7.7) normal (0, 0, 1) x axis (1, 0, 0)
  line L1 (-2.95, -9.65) -> (-6.05, -9.65)
  line L2 (-0.75, -4.35) -> (-0.75, -7.45)
  line L3 (-6.05, -2.15) -> (-2.95, -2.15)
  line L4 (-8.25, -7.45) -> (-8.25, -4.35)
  line L5 (-2.95, -9.05) -> (-6.05, -9.05)
  line L6 (-1.35, -4.35) -> (-1.35, -7.45)
  line L7 (-6.05, -2.75) -> (-2.95, -2.75)
  line L8 (-7.65, -7.45) -> (-7.65, -4.35)
  arc A1 centre (-2.95, -7.45) radius 2.2 clockwise from (-0.75, -7.45) to (-2.95, -9.65)
  arc A2 centre (-2.95, -4.35) radius 2.2 clockwise from (-2.95, -2.15) to (-0.75, -4.35)
  arc A3 centre (-6.05, -4.35) radius 2.2 clockwise from (-8.25, -4.35) to (-6.05, -2.15)
  arc A4 centre (-6.05, -7.45) radius 2.2 clockwise from (-6.05, -9.65) to (-8.25, -7.45)
  arc A5 centre (-2.95, -7.45) radius 1.6 clockwise from (-1.35, -7.45) to (-2.95, -9.05)
  arc A6 centre (-2.95, -4.35) radius 1.6 clockwise from (-2.95, -2.75) to (-1.35, -4.35)
  arc A7 centre (-6.05, -4.35) radius 1.6 clockwise from (-7.65, -4.35) to (-6.05, -2.75)
  arc A8 centre (-6.05, -7.45) radius 1.6 clockwise from (-6.05, -9.05) to (-7.65, -7.45)
extrude "Extrude14" cut sketch "Sketch14" along normal blind 0.3
work_plane "WorkPlane15" AlongDistance -7.7 ExtraOffset 0
sketch "Sketch15" plane through (0, 0, -7.7) normal (0, 0, 1) x axis (1, 0, 0)
  line L1 (-5.7, -7.9) -> (-6.5, -7.9)
  line L2 (-5.7, -7.1) -> (-5.7, -7.9)
  line L3 (-6.5, -7.1) -> (-5.7, -7.1)
  line L4 (-6.5, -7.9) -> (-6.5, -7.1)
  line L5 (-4.1, -7.9) -> (-4.9, -7.9)
  line L6 (-4.1, -7.1) -> (-4.1, -7.9)
  line L7 (-4.9, -7.1) -> (-4.1, -7.1)
  line L8 (-4.9, -7.9) -> (-4.9, -7.1)
  line L9 (-2.5, -7.9) -> (-3.3, -7.9)
  line L10 (-2.5, -7.1) -> (-2.5, -7.9)
  line L11 (-3.3, -7.1) -> (-2.5, -7.1)
  line L12 (-3.3, -7.9) -> (-3.3, -7.1)
  line L13 (-5.7, -6.3) -> (-6.5, -6.3)
  line L14 (-5.7, -5.5) -> (-5.7, -6.3)
  line L15 (-6.5, -5.5) -> (-5.7, -5.5)
  line L16 (-6.5, -6.3) -> (-6.5, -5.5)
  line L17 (-4.1, -6.3) -> (-4.9, -6.3)
  line L18 (-4.1, -5.5) -> (-4.1, -6.3)
  line L19 (-4.9, -5.5) -> (-4.1, -5.5)
  line L20 (-4.9, -6.3) -> (-4.9, -5.5)
  line L21 (-2.5, -6.3) -> (-3.3, -6.3)
  line L22 (-2.5, -5.5) -> (-2.5, -6.3)
  line L23 (-3.3, -5.5) -> (-2.5, -5.5)
  line L24 (-3.3, -6.3) -> (-3.3, -5.5)
  line L25 (-5.7, -4.7) -> (-6.5, -4.7)
  line L26 (-5.7, -3.9) -> (-5.7, -4.7)
  line L27 (-6.5, -3.9) -> (-5.7, -3.9)
  line L28 (-6.5, -4.7) -> (-6.5, -3.9)
  line L29 (-4.1, -4.7) -> (-4.9, -4.7)
  line L30 (-4.1, -3.9) -> (-4.1, -4.7)
  line L31 (-4.9, -3.9) -> (-4.1, -3.9)
  line L32 (-4.9, -4.7) -> (-4.9, -3.9)
  line L33 (-2.5, -4.7) -> (-3.3, -4.7)
  line L34 (-2.5, -3.9) -> (-2.5, -4.7)
  line L35 (-3.3, -3.9) -> (-2.5, -3.9)
  line L36 (-3.3, -4.7) -> (-3.3, -3.9)
extrude "Extrude15" cut sketch "Sketch15" along normal blind 0.3
work_plane "WorkPlane16" AlongDistance -7.7 ExtraOffset 0
sketch "Sketch16" plane through (0, 0, -7.7) normal (0, 0, 1) x axis (1, 0, 0)
  line L1 (6.05, -9.65) -> (2.95, -9.65)
  line L2 (8.25, -4.35) -> (8.25, -7.45)
  line L3 (2.95, -2.15) -> (6.05, -2.15)
  line L4 (0.75, -7.45) -> (0.75, -4.35)
  line L5 (6.05, -9.05) -> (2.95, -9.05)
  line L6 (7.65, -4.35) -> (7.65, -7.45)
  line L7 (2.95, -2.75) -> (6.05, -2.75)
  line L8 (1.35, -7.45) -> (1.35, -4.35)
  arc A1 centre (6.05, -7.45) radius 2.2 clockwise from (8.25, -7.45) to (6.05, -9.65)
  arc A2 centre (6.05, -4.35) radius 2.2 clockwise from (6.05, -2.15) to (8.25, -4.35)
  arc A3 centre (2.95, -4.35) radius 2.2 clockwise from (0.75, -4.35) to (2.95, -2.15)
  arc A4 centre (2.95, -7.45) radius 2.2 clockwise from (2.95, -9.65) to (0.75, -7.45)
  arc A5 centre (6.05, -7.45) radius 1.6 clockwise from (7.65, -7.45) to (6.05, -9.05)
  arc A6 centre (6.05, -4.35) radius 1.6 clockwise from (6.05, -2.75) to (7.65, -4.35)
  arc A7 centre (2.95, -4.35) radius 1.6 clockwise from (1.35, -4.35) to (2.95, -2.75)
  arc A8 centre (2.95, -7.45) radius 1.6 clockwise from (2.95, -9.05) to (1.35, -7.45)
extrude "Extrude16" cut sketch "Sketch16" along normal blind 0.3
work_plane "WorkPlane17" AlongDistance -7.7 ExtraOffset 0
sketch "Sketch17" plane through (0, 0, -7.7) normal (0, 0, 1) x axis (1, 0, 0)
  line L1 (4.375, -8.325) -> (3.775, -8.325)
  line L2 (4.375, -7.725) -> (4.375, -8.325)
  line L3 (3.775, -7.725) -> (4.375, -7.725)
  line L4 (3.775, -8.325) -> (3.775, -7.725)
  line L5 (6.075, -8.325) -> (5.475, -8.325)
  line L6 (6.075, -7.725) -> (6.075, -8.325)
  line L7 (5.475, -7.725) -> (6.075, -7.725)
  line L8 (5.475, -8.325) -> (5.475, -7.725)
  line L9 (3.525, -7.475) -> (2.925, -7.475)
  line L10 (3.525, -6.875) -> (3.525, -7.475)
  line L11 (2.925, -6.875) -> (3.525, -6.875)
  line L12 (2.925, -7.475) -> (2.925, -6.875)
  line L13 (5.225, -7.475) -> (4.625, -7.475)
  line L14 (5.225, -6.875) -> (5.225, -7.475)
  line L15 (4.625, -6.875) -> (5.225, -6.875)
  line L16 (4.625, -7.475) -> (4.625, -6.875)
  line L17 (6.925, -7.475) -> (6.325, -7.475)
  line L18 (6.925, -6.875) -> (6.925, -7.475)
  line L19 (6.325, -6.875) -> (6.925, -6.875)
  line L20 (6.325, -7.475) -> (6.325, -6.875)
  line L21 (2.675, -6.625) -> (2.075, -6.625)
  line L22 (2.675, -6.025) -> (2.675, -6.625)
  line L23 (2.075, -6.025) -> (2.675, -6.025)
  line L24 (2.075, -6.625) -> (2.075, -6.025)
  line L25 (4.375, -6.625) -> (3.775, -6.625)
  line L26 (4.375, -6.025) -> (4.375, -6.625)
  line L27 (3.775, -6.025) -> (4.375, -6.025)
  line L28 (3.775, -6.625) -> (3.775, -6.025)
  line L29 (6.075, -6.625) -> (5.475, -6.625)
  line L30 (6.075, -6.025) -> (6.075, -6.625)
  line L31 (5.475, -6.025) -> (6.075, -6.025)
  line L32 (5.475, -6.625) -> (5.475, -6.025)
  line L33 (3.525, -5.775) -> (2.925, -5.775)
  line L34 (3.525, -5.175) -> (3.525, -5.775)
  line L35 (2.925, -5.175) -> (3.525, -5.175)
  line L36 (2.925, -5.775) -> (2.925, -5.175)
  line L37 (5.225, -5.775) -> (4.625, -5.775)
  line L38 (5.225, -5.175) -> (5.225, -5.775)
  line L39 (4.625, -5.175) -> (5.225, -5.175)
  line L40 (4.625, -5.775) -> (4.625, -5.175)
  line L41 (6.925, -5.775) -> (6.325, -5.775)
  line L42 (6.925, -5.175) -> (6.925, -5.775)
  line L43 (6.325, -5.175) -> (6.925, -5.175)
  line L44 (6.325, -5.775) -> (6.325, -5.175)
  line L45 (2.675, -4.925) -> (2.075, -4.925)
  line L46 (2.675, -4.325) -> (2.675, -4.925)
  line L47 (2.075, -4.325) -> (2.675, -4.325)
  line L48 (2.075, -4.925) -> (2.075, -4.325)
  line L49 (4.375, -4.925) -> (3.775, -4.925)
  line L50 (4.375, -4.325) -> (4.375, -4.925)
  line L51 (3.775, -4.325) -> (4.375, -4.325)
  line L52 (3.775, -4.925) -> (3.775, -4.325)
  line L53 (6.075, -4.925) -> (5.475, -4.925)
  line L54 (6.075, -4.325) -> (6.075, -4.925)
  line L55 (5.475, -4.325) -> (6.075, -4.325)
  line L56 (5.475, -4.925) -> (5.475, -4.325)
  line L57 (3.525, -4.075) -> (2.925, -4.075)
  line L58 (3.525, -3.475) -> (3.525, -4.075)
  line L59 (2.925, -3.475) -> (3.525, -3.475)
  line L60 (2.925, -4.075) -> (2.925, -3.475)
  line L61 (5.225, -4.075) -> (4.625, -4.075)
  line L62 (5.225, -3.475) -> (5.225, -4.075)
  line L63 (4.625, -3.475) -> (5.225, -3.475)
  line L64 (4.625, -4.075) -> (4.625, -3.475)
extrude "Extrude17" cut sketch "Sketch17" along normal blind 0.3
work_plane "WorkPlane18" AlongDistance -7.7 ExtraOffset 0
sketch "Sketch18" plane through (0, 0, -7.7) normal (0, 0, 1) x axis (1, 0, 0)
  line L1 (15.05, -9.65) -> (11.95, -9.65)
  line L2 (17.25, -4.35) -> (17.25, -7.45)
  line L3 (11.95, -2.15) -> (15.05, -2.15)
  line L4 (9.75, -7.45) -> (9.75, -4.35)
  arc A1 centre (15.05, -7.45) radius 2.2 clockwise from (17.25, -7.45) to (15.05, -9.65)
  arc A2 centre (15.05, -4.35) radius 2.2 clockwise from (15.05, -2.15) to (17.25, -4.35)
  arc A3 centre (11.95, -4.35) radius 2.2 clockwise from (9.75, -4.35) to (11.95, -2.15)
  arc A4 centre (11.95, -7.45) radius 2.2 clockwise from (11.95, -9.65) to (9.75, -7.45)
extrude "Extrude18" cut sketch "Sketch18" along normal blind 0.3
work_plane "WorkPlane1" AlongDistance -5.8 ExtraOffset 0
sketch "Sketch1" plane through (0, 0, -5.8) normal (0, 0, 1) x axis (1, 0, 0)
  line L1 (8.4, -6.9) -> (-21.6, -6.9)
  line L2 (8.4, 13.1) -> (8.4, -6.9)
  line L3 (-21.6, 13.1) -> (8.4, 13.1)
  line L4 (-21.6, -6.9) -> (-21.6, 13.1)
extrude "Extrude1" new body sketch "Sketch1" along normal blind 5 bodies "LiPo 30x20x5"
work_plane "WorkPlane2" AlongDistance -6.5 ExtraOffset 0
sketch "Sketch2" plane through (0, 0, -6.5) normal (0, 0, 1) x axis (1, 0, 0)
  circle C1 centre (15.5, 4) radius 5
extrude "Extrude2" new body sketch "Sketch2" along normal blind 2.7 bodies "Vibration motor 10x2.7"
work_plane "WorkPlane3" AlongDistance -1.3 ExtraOffset 0
sketch "Sketch3" plane through (0, 0, -1.3) normal (0, 0, 1) x axis (1, 0, 0)
  line L1 (21.6, -24.9) -> (0.6, -24.9)
  line L2 (21.6, -7.1) -> (21.6, -24.9)
  line L3 (0.6, -7.1) -> (21.6, -7.1)
  line L4 (0.6, -24.9) -> (0.6, -7.1)
extrude "Extrude3" new body sketch "Sketch3" along normal blind 1 bodies "XIAO ESP32-S3 (upside down)"
work_plane "WorkPlane4" AlongDistance -4.5 ExtraOffset 0
sketch "Sketch4" plane through (0, 0, -4.5) normal (0, 0, 1) x axis (1, 0, 0)
  line L1 (22, -20.45) -> (14.6, -20.45)
  line L2 (22, -11.55) -> (22, -20.45)
  line L3 (14.6, -11.55) -> (22, -11.55)
  line L4 (14.6, -20.45) -> (14.6, -11.55)
extrude "Extrude4" add sketch "Sketch4" along normal blind 3.2
work_plane "WorkPlane5" AlongDistance -3.8 ExtraOffset 0
sketch "Sketch5" plane through (0, 0, -3.8) normal (0, 0, 1) x axis (1, 0, 0)
  line L1 (14.6, -23.9) -> (1.6, -23.9)
  line L2 (14.6, -8.1) -> (14.6, -23.9)
  line L3 (1.6, -8.1) -> (14.6, -8.1)
  line L4 (1.6, -23.9) -> (1.6, -8.1)
extrude "Extrude5" add sketch "Sketch5" along normal blind 2.5
work_plane "WorkPlane6" AlongDistance -6.5 ExtraOffset 0
sketch "Sketch6" plane through (0, 0, -6.5) normal (0, 0, 1) x axis (1, 0, 0)
  line L1 (-3.5, -24.9) -> (-17.5, -24.9)
  line L2 (-3.5, -10.9) -> (-3.5, -24.9)
  line L3 (-17.5, -10.9) -> (-3.5, -10.9)
  line L4 (-17.5, -24.9) -> (-17.5, -10.9)
extrude "Extrude6" new body sketch "Sketch6" along normal blind 6.2 bodies "DS3231 14x14 (no header)"
work_plane "WorkPlane7" AlongDistance -6.8 ExtraOffset 0
sketch "Sketch7" plane through (0, 0, -6.8) normal (0, 0, 1) x axis (1, 0, 0)
  circle C1 centre (11, -15.3) radius 10
extrude "Extrude7" new body sketch "Sketch7" along normal blind 0.5 bodies "Piezo disc 20mm"
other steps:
create_component "CreateComponent1"
create_component "CreateComponent50"
create_component "CreateComponent51"
create_component "CreateComponent52"
named bodies: "Shell", "Back", "LiPo 30x20x5", "Vibration motor 10x2.7", "XIAO ESP32-S3 (upside down)", "DS3231 14x14 (no header)", "Piezo disc 20mm"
